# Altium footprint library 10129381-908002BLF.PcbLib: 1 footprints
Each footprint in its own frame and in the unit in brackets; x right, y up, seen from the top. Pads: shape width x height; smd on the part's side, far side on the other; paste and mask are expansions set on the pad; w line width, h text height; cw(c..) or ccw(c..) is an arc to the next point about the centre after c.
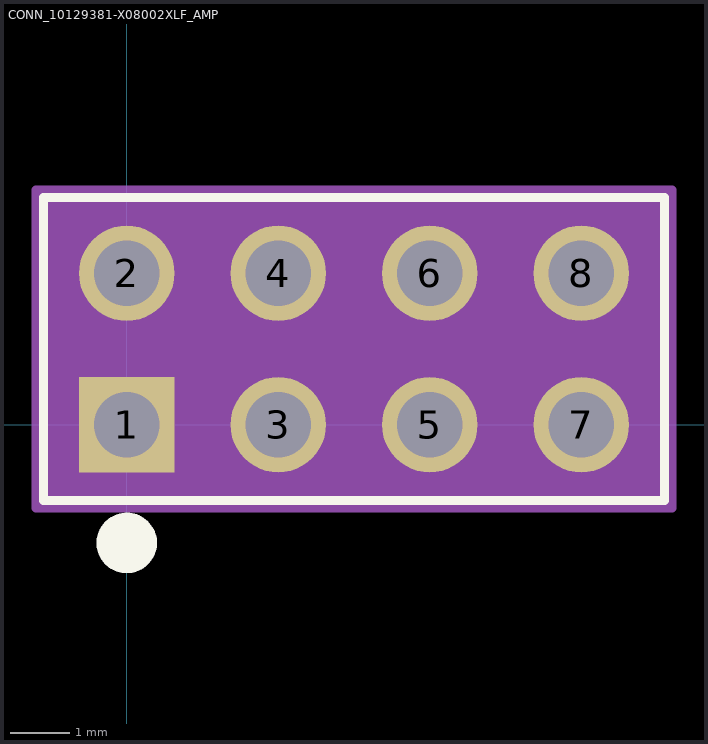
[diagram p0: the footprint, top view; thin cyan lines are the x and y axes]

## CONN_10129381-X08002XLF_AMP [mil]
pads (8):
  rect 63x63 hole 43 paste-31.5 mask+0: 1(0,0)
  round 63 hole 43 paste-31.5 mask+0: 2(0,100) 3(100,0) 4(100,100) 5(200,0) 6(200,100) 7(300,0) 8(300,100)
Top Overlay:
  circle w20: c0,-78 r10
  lines w6: -55,-50 355,-50 355,150 -55,150 -55,-50
  text ".Designator" at 12.5,25 h50
Mechanical 13:
  circle w1: c0,-30 r10
  lines w1: -50,-45 350,-45 350,145 -50,145 -50,-45
  text ".Designator" at 12.5,25 h50
Mechanical 15:
  region: 360,155 -60,155 -60,-55 360,-55
  lines w6: -60,-55 -60,155 360,155 360,-55 -60,-55
3D body "CONN_10129381-X08002XLF_AMP.step": height 337.99, standoff -200, extent -50,-150 350,50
